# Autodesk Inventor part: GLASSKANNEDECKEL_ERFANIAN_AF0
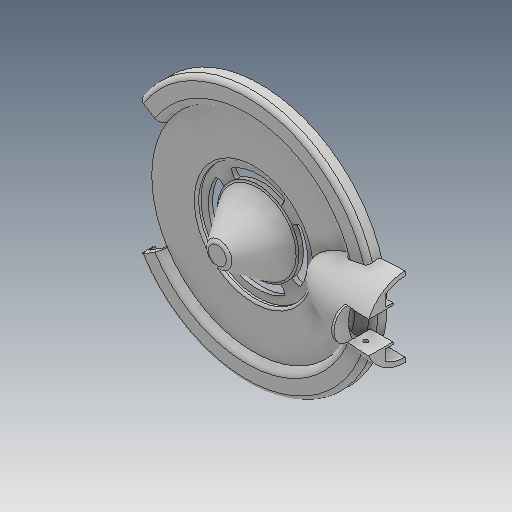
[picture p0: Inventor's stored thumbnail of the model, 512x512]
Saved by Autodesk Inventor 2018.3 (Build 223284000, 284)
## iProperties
Created: 2019-01
Part Number: GLASSKANNEDECKEL_ERFANIAN_AF0
Material: Steel, High strength low alloy (HSLA)
Document SubType Name: Modeling
Designer: zand
Density: 7.84984 g/cm^3
Appearance: Vorgabe
Mass: 198.444 g
Surface Area: 261.373 cm^2
Volume: 25.2801 cm^3
Author: zand
Revision Number: 20LAST_VERSION
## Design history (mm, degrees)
feature "Basis1"
node "Volumenkörper1"
